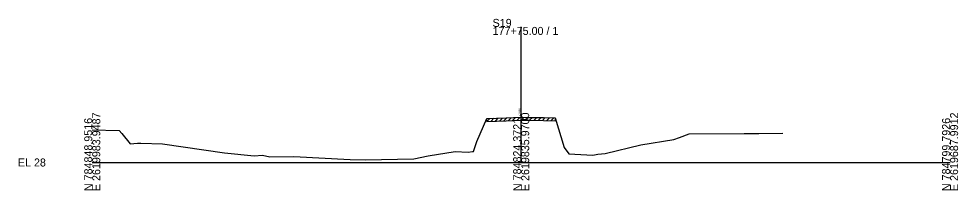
# Model space of a CAD drawing. Extents: x 1274 to 1603, y -10 to 1051.
# Drawn here: x 1274.3 to 1602.9, y 490.3 to 550.3 of the extents above; entities that cross this region are included whole.
import ezdxf

# ---------------------------------------------------------------- set-up
doc = ezdxf.new("R2010")
doc.units = 0
for name, color, linetype in [('RD_GPK_XS_Cell', 7, 'Continuous'), ('RD_XS_ExGround', 7, 'Continuous'), ('RD_XS_ExPaveRet', 7, 'Continuous'), ('RD_XS_TX_Elev_EX', 7, 'Continuous')]:
    doc.layers.add(name, color=color, linetype=linetype)

msp = doc.modelspace()

# ---------------------------------------------------------------- linework, layer by layer
at = {"layer": 'RD_GPK_XS_Cell'}
for p, q in [((1450.01, 500), (1450.01, 547.42)), ((1300, 500), (1450.01, 500)), ((1450.01, 500), (1600.01, 500))]:
    msp.add_line(p, q, dxfattribs=at)
at = {"layer": 'RD_XS_ExGround'}
for p, q in [((1434.46, 507.33), (1437.96, 515.38)), ((1437.96, 515.38), (1444.8, 515.57)), ((1444.8, 515.57), (1449.89, 515.81)), ((1449.89, 515.81), (1451.51, 515.78)), ((1451.51, 515.78), (1457.82, 515.71)), ((1457.82, 515.71), (1461.88, 515.62)), ((1461.88, 515.62), (1465.08, 505.24)), ((1300, 511.38), (1309.42, 511.24)), ((1309.42, 511.24), (1310.4, 510.13)), ((1310.4, 510.13), (1313.29, 506.58)), ((1505.33, 508.77), (1508.72, 509.98)), ((1508.72, 509.98), (1527.97, 510.1)), ((1527.97, 510.1), (1530.96, 510.11)), ((1530.96, 510.11), (1533.09, 510.09)), ((1533.09, 510.09), (1541.46, 510.2)), ((1313.29, 506.58), (1315.78, 506.81)), ((1315.78, 506.81), (1317.04, 506.76)), ((1317.04, 506.76), (1324.53, 506.49)), ((1324.53, 506.49), (1346.21, 503.42)), ((1433.28, 503.87), (1434.46, 507.33)), ((1479.43, 503.1), (1491.86, 506.23)), ((1491.86, 506.23), (1503.43, 507.99)), ((1503.43, 507.99), (1505.33, 508.77)), ((1346.21, 503.42), (1356.66, 502.34)), ((1417.44, 502.38), (1426.89, 503.79)), ((1426.89, 503.79), (1431.52, 503.57)), ((1431.52, 503.57), (1432.93, 503.84)), ((1432.93, 503.84), (1433.28, 503.87)), ((1465.08, 505.24), (1466.7, 503.01)), ((1466.7, 503.01), (1475.05, 502.53)), ((1475.05, 502.53), (1476.8, 502.93)), ((1476.8, 502.93), (1479.43, 503.1)), ((1356.66, 502.34), (1359.58, 502.6)), ((1359.58, 502.6), (1362.12, 502.02)), ((1362.12, 502.02), (1370.46, 502.13)), ((1370.46, 502.13), (1390.19, 501.03)), ((1390.19, 501.03), (1395.45, 500.97)), ((1395.45, 500.97), (1412.45, 501.29)), ((1412.45, 501.29), (1417.44, 502.38))]:
    msp.add_line(p, q, dxfattribs=at)
at = {"layer": 'RD_XS_ExPaveRet'}
for p, q in [((1437.96, 514.38), (1438.99, 515.41)), ((1437.96, 514.38), (1437.96, 515.38)), ((1437.96, 514.38), (1444.8, 514.57)), ((1439.46, 514.42), (1440.49, 515.45)), ((1440.96, 514.46), (1441.99, 515.49)), ((1442.46, 514.51), (1443.49, 515.53)), ((1443.96, 514.55), (1445, 515.58)), ((1444.8, 514.57), (1449.89, 514.81)), ((1445.46, 514.6), (1446.51, 515.65)), ((1446.96, 514.67), (1448.01, 515.72)), ((1448.46, 514.74), (1449.51, 515.79)), ((1449.89, 514.81), (1451.51, 514.78)), ((1449.96, 514.8), (1450.95, 515.79)), ((1451.46, 514.78), (1452.45, 515.77)), ((1451.51, 514.78), (1457.82, 514.71)), ((1452.96, 514.76), (1453.95, 515.75)), ((1454.46, 514.74), (1455.45, 515.73)), ((1455.96, 514.73), (1456.95, 515.72)), ((1457.46, 514.71), (1458.45, 515.69)), ((1457.82, 514.71), (1461.88, 514.62)), ((1458.96, 514.68), (1459.94, 515.66)), ((1460.46, 514.65), (1461.44, 515.63)), ((1461.88, 515.62), (1461.88, 514.62))]:
    msp.add_line(p, q, dxfattribs=at)

# ---------------------------------------------------------------- texts
at = {"layer": 'RD_GPK_XS_Cell'}
for s, p in [('S19', (1440.01, 547.42)), ('177+75.00 / 1', (1440.01, 544.62)), ('EL 28', (1274, 498.6))]:
    msp.add_text(s, height=2.8, dxfattribs=at).set_placement(p)
for s, p in [('E 2619983.9487', (1302.8, 490)), ('E 2619835.9700', (1452.81, 490)), ('E 2619687.9912', (1602.81, 490)), ('N 784848.9516', (1300, 490)), ('N 784824.3721', (1450.01, 490)), ('N 784799.7926', (1600.01, 490))]:
    msp.add_text(s, height=2.8, rotation=90, dxfattribs=at).set_placement(p)
at = {"layer": 'RD_XS_TX_Elev_EX'}
msp.add_text('43.80', height=0.8, rotation=90, dxfattribs=at).set_placement((1449.91, 516.3))

doc.saveas('drawing.dxf')
